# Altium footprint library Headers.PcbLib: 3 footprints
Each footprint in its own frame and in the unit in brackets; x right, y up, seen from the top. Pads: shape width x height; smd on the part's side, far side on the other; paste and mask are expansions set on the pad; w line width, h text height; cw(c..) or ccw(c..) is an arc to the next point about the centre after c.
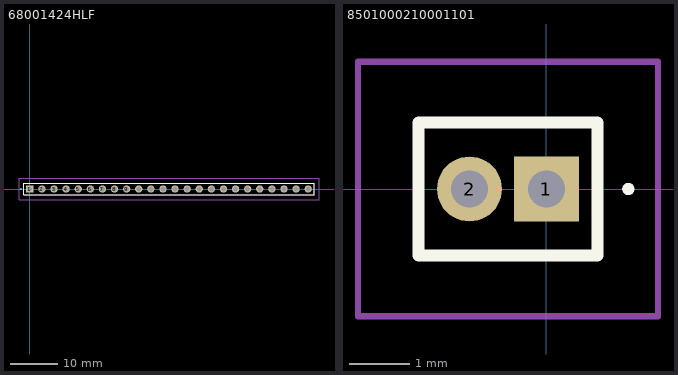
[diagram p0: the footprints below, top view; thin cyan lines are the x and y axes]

## 68001424HLF [mm]
pads (24):
  rect 1.53x1.53 hole 1.02: 1(0,0)
  round 1.53 hole 1.02: 2(2.54,0) 3(5.08,0) 4(7.62,0) 5(10.16,0) 6(12.7,0) 7(15.24,0) 8(17.78,0) 9(20.32,0) 10(22.86,0) 11(25.4,0) 12(27.94,0) 13(30.48,0) 14(33.02,0) 15(35.56,0) 16(38.1,0) 17(40.64,0) 18(43.18,0) 19(45.72,0) 20(48.26,0) 21(50.8,0) 22(53.34,0) 23(55.88,0) 24(58.42,0)
Top Overlay:
  lines w0.1: -1.9,0 ccw(c-1.85,0) -1.8,0 ccw(c-1.85,0) -1.9,0
  lines w0.2: -1.27,-1.205 -1.27,1.205 59.69,1.205 59.69,-1.205 -1.27,-1.205
Mechanical 13:
  lines w0.1: -1.27,-1.205 -1.27,1.205 59.69,1.205 59.69,-1.205 -1.27,-1.205
Mechanical 15:
  lines w0.1: -2.27,-2.205 -2.27,2.205 60.69,2.205 60.69,-2.205 -2.27,-2.205
3D body "68001-424HLF.stp": height 1.21, standoff -1.21, extent -1.27,-3.251 49.53,8.179

## 8501000210001101 [mm]
pads (2):
  rect 1.07x1.07 hole 0.61: 1(0,0)
  round 1.07 hole 0.61: 2(-1.27,0)
Top Overlay:
  lines w0.1: 1.3,0 ccw(c1.35,0) 1.4,0 ccw(c1.35,0) 1.3,0
  lines w0.2: -2.11,-1.1 0.84,-1.1 0.84,1.1 -2.11,1.1 -2.11,-1.1
Mechanical 13:
  lines w0.1: -2.11,-1.1 0.84,-1.1 0.84,1.1 -2.11,1.1 -2.11,-1.1
Mechanical 15:
  lines w0.1: -3.11,-2.1 -3.11,2.1 1.84,2.1 1.84,-2.1 -3.11,-2.1
3D body "850-10-002-10-001101.stp": height 5.16, standoff -2.94, extent -2.115,-1.1 0.835,1.1

## PCBComponent_1 [mil]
